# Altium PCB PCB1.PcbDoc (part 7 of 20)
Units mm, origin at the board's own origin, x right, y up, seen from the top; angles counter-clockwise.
Board outline 294.51 x 138.18 mm, 12 copper layers (Top Layer 1 _Signal, L2_GND, L3_Signals, L4_GND, L5_POWER, L6_Signals, L7_GND, L8_Signals, L9_GND, L10_POWER, L11_GND, Bottom Layer_Signals), stack 1.788 mm thick; 1254 components, 836 nets, 5699 pads, 2073 vias.
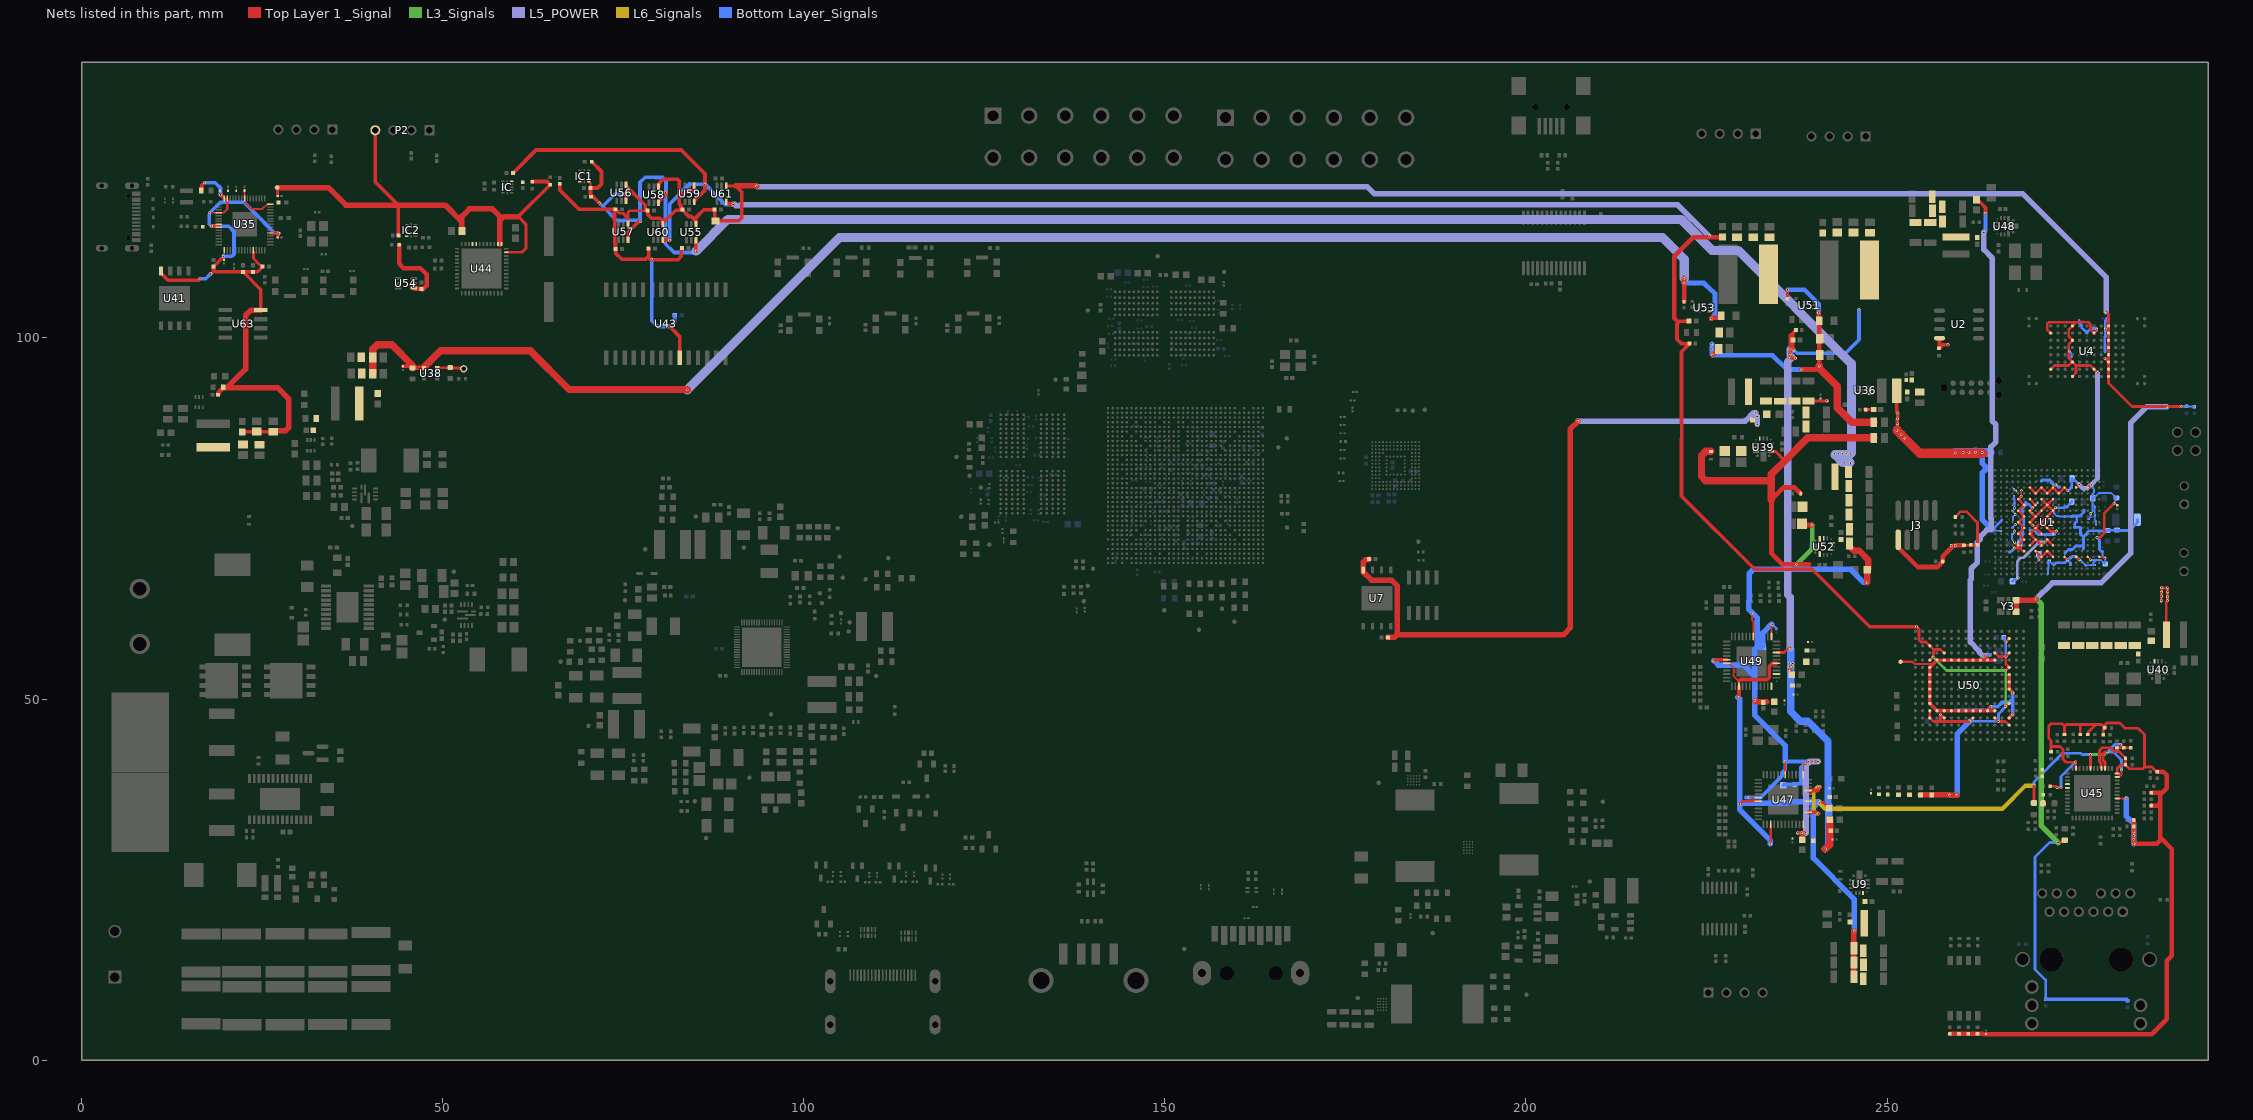
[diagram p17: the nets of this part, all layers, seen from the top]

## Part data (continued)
SW1: library part SWITCH1051, "Switch DIP", Manufacturer 1="Copal Electronics", Manufacturer Part Number 1=CHS-04TB, Supplier Part Number 1=563-1008-1-ND
SW3 SW4 SW5 SW6 SW7 SW8 SW9 SW10 SW11: library part CMP-10040-000021-1, "SWITCH TACTILE SPST-NO 0.05A 32V", Case/Package=SMD/SMT, Current Rating=50mA, Max Operating Temperature=85°C, Max Voltage Rating (DC)=32V, Min Operating Temperature=-40°C, Operating Force=4N, Package Quantity=6000, Power Rating=1W
TP2 TP6 TP7 TP8 TP9 TP10 TP13 TP14 TP15 TP16 TP17 TP18 TP20 TP22 TP23 TP25 TP27 TP28 TP29 TP31 TP35 TP36 TP37 TP38 TP39 TP41 TP42 TP43 TP45 TP46 TP48 TP49 TP50 TP51 TP52 TP53 TP54 TP55 TP56 TP57 TP59 TP60 TP61 TP62 TP63 TP64 TP65 TP66 TP67 TP68 TP71 TP72 TP74 TP75 TP76 TP81 TP82 TP83: library part CMP-00028-00002-2, "0.6mm round"
TP21: library part CON1885, "Test Point"
U1: library part MIC9729, Manufacturer 1="Microchip Technology", Operating Temperature="-40C to 85C"
U2: library part MIC9680, Manufacturer 1="Microchip Technology", Manufacturer Part Number 1=SST26WF016BT-104I/SN, Operating Temperature="-40°C ~ 85°C"
U3: "low power, high performance processor", Package=None
U4: library part IC1641, Manufacturer 1=Flexxon, Manufacturer 4=ISSI, Manufacturer Part Number 1=FEMC004GTTE7-T13-17, Manufacturer Part Number 2=FEMC004GTTE7-T13-18, Manufacturer Part Number 3=FEMC004GTTE7-T13-16, Manufacturer Part Number 4=IS21ES04G-JQLI, Operating Temperature="-40C to +85C", Package=FBGA-100, Supplier Part Number 1=3052-FEMC004GTTE7-T13-17-ND
U5: "RK806-1 Power Management IC", Package=None
U6 U63: "Security ICs / Authentication ICs ECC/ECDH, I2C, SOIC T/R", Package="SO-8 Microchip"
U7: "FLASH - NOR Memory IC 512Mb (64M x 8) SPI - Quad I/O 133 MHz 8-WSON (8x6)", Package=Package
U8: library part CMP-0078-00029-4, "IC USB FS SERIAL UART 28-SSOP", Case/Package=SSOP, Max Operating Temperature=85°C, Max Supply Voltage=5.25V, Min Operating Temperature=-40°C, Min Supply Voltage=3.3V, Operating Supply Current=15mA, Package Quantity=2000, Voltage=5V
U9 U39 U40 U48 U52: "17V VIN, 8A low-noise low-ripple buck converter with integrated ferrite-bead filter compensation 14-VQFN-HR -40 to 150", Manufacturer_Name="Texas Instruments"
U10: JLCPCB Part Class="Extended Part", Manufacturer=SANDISK(闪迪)
U11: library part SDCW2012-2-900TF
U12 U15: library part FLXC2004G-N1
U13 U14 U16 U17 U29 U33: library part ESD5341N
U18 U19: library part MP8759GD-Z
U20 U21: library part ESD5304D
U25: library part SY8089AAC
U26 U27: library part SGM2576YN5G/TR
U28: "-40℃~+125℃@(TJ) 1 120uA 3V~16V 600kHz 600mV~7V 6A Adjustable Buck Buck Built-in Yes SOT-563 DC-DC Converters ROHS", Package=SOT-563
U34: "-40℃~+125℃@(TJ) 1 3V~16V 400uA 600kHz 600mV~7V 6A Adjustable Buck Buck Built-in Yes SOT-563 DC-DC Converters ROHS", Package=SOT-563
U35: library part RP2350A
U37: library part C9002, Case=SMD3225-4P
U38: library part MIC7045, Manufacturer 1="Microchip Technology", Manufacturer Part Number 1=MIC5377YC5-TR, Operating Temperature="-40C to +125C", Supplier Part Number 1=576-3358-1-ND
U41: library part "W25Q128JVEIQ TR"
U42: library part CMP-0063-01545-2, "High Voltage System Power Management and Protection IC with PMBus, 28-pin TSSOP-EP, 2500 Reel", Manufacturer="Texas Instruments", PackageTopMarking=NSUZXYTTE#*LM5066PMH, PowerWise=Y
U43: library part CMP-0186-00060-3, "IC I/O EXPANDER I2C 16B 28SOIC", Case/Package=SOIC, Frequency=1.7MHz, Max Operating Temperature=125°C, Min Operating Temperature=-40°C, Nominal Supply Current=1mA, Operating Supply Voltage=5.5V, Package Quantity=1600
U44: "-40℃~+85℃ 1.71V~3.6V、1.71V~3.6V、2.35V~3.6V 128Byte 12Mbps 4 I2C、SPI、IrDA、RS-485、RS-232 With automatic flow control、Configurable GPIO、Auto Transceiver Direction Control、Interrupt Trigger TQFN-48-EP(7x7) UART ROHS", Case=TQFN-48-EP(7x7)
U45: library part MIC8558, Manufacturer 1="Microchip Technology", Manufacturer Part Number 1=LAN8840/PSA
U46: library part SXMH3.6864F2020F30, Case/Package=HC-49S-SMD
U47 U49: library part CMP-04874-000002-2, "IC TRANSCEIVER 1/1 48FN"
U50: library part CMP-06281-000140-1, "IC TELECOM INTERFACE 256BGA", Case/Package=BGA
U51 U53: library part TPS565247DRLR
U54 U55 U56 U57 U58 U59 U60 U61: library part CMP-00370-128857311-1, "Single channel fixed-direction level shifter 6-SC70 -40 to 125", Ambient Temperature Range High=125°C, Manufacturer Lifecycle Status=ACTIVE, Max Junction Temperature (Tj)=150°C, Min Operating Temperature=-40°C, Nominal Supply Current=2.5µA
U62: library part CMP-0069-01417-3, "Wide Range Synchronous Buck Controller, 20-pin TSSOP-EP, Pb-Free", Manufacturer="Texas Instruments", PackageTopMarking=NSUZXYTT*LM25116*MH, PowerWise=Y
USB1: library part HMT-MINIUSB-5PTP
USBC1: "USB Connectors 24 Receptacle 1 8.94*7.3mm RoHS", Package=Package
X1: library part X322524MSB4SI, "X322524MSB4SI"
Y2 Y4: library part CMP-27762-015150-1, "Crystal 25MHz ±20ppm (Tol) ±100ppm (Stability) 12pF FUND 50Ω Automotive 4-Pin Ultra Mini-CSMD T/R", Case/Package=SMD/SMT, ESR (Equivalent Series Resistance)=50R, Frequency=25MHz, Frequency Stability=100ppm, Frequency Tolerance=20ppm, LCSC=C1985412, Load Capacitance=12pF, Max Operating Temperature=125°C, Min Operating Temperature=-40°C, Ratings=AEC-Q200
Y3: library part CMP-06265-000025-1, "MEMS OSC XO 125.0000MHZ LVDS SMD", Case/Package=SMD/SMT, Frequency=125MHz, Frequency Stability=25ppm, Load Capacitance=2pF, Max Operating Temperature=85°C, Max Supply Current=32mA, Max Supply Voltage=3.6V, Min Operating Temperature=-40°C, Min Supply Voltage=2.25V, Package Quantity=1000, Ratings=AEC-Q100

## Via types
v1: diameter 0.4, hole 0.2, Top Layer 1 _Signal to Bottom Layer_Signals, 2009 vias
v2: diameter 0.508, hole 0.254, Top Layer 1 _Signal to Bottom Layer_Signals, 36 vias
v3: diameter 0.5, hole 0.2, Top Layer 1 _Signal to Bottom Layer_Signals, 12 vias
v4: diameter 1.27, hole 0.711, Top Layer 1 _Signal to Bottom Layer_Signals, 6 vias
v5: diameter 0.3, hole 0.2, Top Layer 1 _Signal to Bottom Layer_Signals, 5 vias
v6: diameter 0.254, hole 0.2, Top Layer 1 _Signal to Bottom Layer_Signals, 3 vias
v7: diameter 0.305, hole 0.2, Top Layer 1 _Signal to Bottom Layer_Signals, 1 vias
v8: diameter 0.254, hole 0.152, Top Layer 1 _Signal to Bottom Layer_Signals, 1 vias

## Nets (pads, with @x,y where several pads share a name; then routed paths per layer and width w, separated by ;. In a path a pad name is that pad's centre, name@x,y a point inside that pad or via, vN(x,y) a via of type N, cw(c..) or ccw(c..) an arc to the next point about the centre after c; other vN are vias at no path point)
0V9: C132.2 C133.2 C136.1 C137.1 C138.1 C139.1 C140.1 C141.1 C142.1 C143.1 C144.1 C145.1 C146.1 C147.1 C148.1 C149.1 C150.1 C151.1 C152.1 C153.1 C154.1 C155.1 C156.1 C190.1 C191.1 C491.2 C635.2 C636.2 C638.2 C639.2 C640.2 FB4.1 FB5.1 FB6.1 FB7.1 L23.2 R158.2 R160.1 U1.J6 U1.J8 U1.J10 U1.J12 U1.J14 U1.K7 U1.K9 U1.K11 U1.K13 U1.L6 U1.L8 U1.L10 U1.L12 U1.L14 U1.M7 U1.M9 U1.M11 U1.M13 U1.N6 U1.N8 U1.N10 U1.N12 U1.N14 U40.4 | length 84.1
  Top Layer 1 _Signal w0.381: U1.N14@269.781,71.28 U1.M13@270.581,72.08 ; U1.N6@269.781,77.68 U1.M7@270.581,76.88 270.568,76.88 270.127,76.439 v1(270.122,76.439) 270.122,76.434 269.781,76.093 U1.N8@269.781,76.08 269.781,75.975 270.07,75.686 v1(270.07,75.681) ; v1(270.2,74.022) 270.2,74.027 269.781,74.446 U1.N10@269.781,74.48 270.473,75.172 270.473,75.277 v1(270.07,75.681) ; U1.L12@271.381,72.88 U1.M11@270.581,73.68 ; U1.L6@271.381,77.68 U1.K7@272.181,76.88 ; v1@271.863,71.762 U1.K13@272.181,72.08 U1.J14@272.981,71.28 ; v1(271.886,71.74) 271.881,71.74 271.421,71.28 U1.L14@271.381,71.28 U1.M13@270.581,72.08 ; U1.J12@272.981,72.88 272.62,73.241 ; U1.J10@272.981,74.48 U1.K9@272.181,75.28 ; U1.J6@272.981,77.68 U1.K7@272.181,76.88 ; v1(273.316,76.478) 273.316,76.472 272.981,76.137 U1.J8@272.981,76.08 ; v1(273.459,73.251) 273.454,73.251 273.443,73.241 272.62,73.241 ; v1(287.967,63.59) 287.967,63.595 287.995,63.623 287.995,64.261 v1(287.999,64.264) v1(287.999,64.813) 287.999,64.818 288.027,64.846 288.027,65.408 v1(288.03,65.412) 288.036,65.412 288.067,65.38 v1(288.863,65.38) 288.863,65.375 288.854,65.366 288.854,64.829 v1(288.85,64.825) 288.85,64.82 288.844,64.814 v1(288.844,64.157) 288.844,64.152 288.828,64.137 288.828,63.619 v1(288.825,63.615) 288.825,63.59 288.674,63.439 L23.2@288.674,58.913 ; v1(270.07,75.681) 270.075,75.681 270.476,75.28 U1.M9@270.581,75.28 U1.L8@271.381,76.08 U1.K7@272.181,76.88 ; U1.M13@270.581,72.08 U1.N12@269.781,72.88 U1.M11@270.581,73.68 ; U1.M11@270.581,73.68 U1.L10@271.381,74.48 ; U1.L10@271.381,74.48 U1.K11@272.181,73.68 272.62,73.241 ; U1.L10@271.381,74.48 U1.K9@272.181,75.28 ; U1.K9@272.181,75.28 U1.J8@272.981,76.08 ; U1.K7@272.181,76.88 U1.J8@272.981,76.08
  L5_POWER w0.381: v1(268.15,66.798) 268.15,66.804 268.022,66.932 268.022,69.007 268.203,69.188 268.203,69.287 268.481,69.565 268.903,69.565 271.078,71.74 v1(271.886,71.74)
  Bottom Layer_Signals w0.254: v1(273.316,76.478) 273.316,76.438 273.123,76.245 273.123,75.79 C137.1@273.11,75.777 273.11,75.767 273.289,75.587 273.289,75.539 273.485,75.343 273.918,75.343 274.001,75.259 C141.1@274.576,75.259 274.589,75.272 275.018,75.272 275.088,75.343 275.144,75.287 275.638,75.287 C146.1@275.651,75.274
  Bottom Layer_Signals w0.381: FB6.1@267.381,66.293 267.381,66.338 267.59,66.547 267.894,66.547 268.145,66.798 v1(268.15,66.798) 268.15,66.792 v1@268.026,66.668 ; FB5.1@268.371,71.513 268.371,71.479 268.389,71.461 268.537,71.609 268.537,72.318 268.737,72.519 268.737,72.695 268.748,72.705 C148.1@268.748,73.766 268.92,73.939 C144.1@268.92,74.922 268.92,75.343 268.739,75.523 C150.1@268.739,75.944 268.739,76.362 269.193,76.816 C142.1@269.193,77.233 269.446,76.981 269.574,76.981 270.117,76.439 v1(270.122,76.439) ; C143.1@269.813,73.353 270.415,73.353 C152.1@270.979,72.788 271.845,72.788 271.909,72.725 C151.1@271.967,72.725 272.03,72.788 273.181,72.788 C138.1@273.186,72.793 273.186,72.973 273.459,73.246 v1(273.459,73.251) ; C191.1@271.233,71.264 271.405,71.264 271.881,71.74 v1(271.886,71.74) ; v1(273.316,76.478) 274.467,76.478 274.586,76.597 274.982,76.597 274.982,76.701 274.997,76.701 274.997,76.729 275.004,76.729 275.564,77.289 FB4.1@275.564,77.334 ; C154.1@274.65,70.14 274.65,70.23 275.137,70.717 275.659,70.717 276.126,71.183 277.034,71.183 277.195,71.022 ; C146.1@275.651,75.274 275.731,75.354 276.286,75.354 ; C190.1@277.165,70.759 277.195,70.789 277.195,71.022 ; C155.1@277.278,76.158 277.278,75.911 C156.1@276.773,75.406 276.722,75.354 276.286,75.354 ; C133.2@280.542,73.346 C133.2@280.579,73.384 ; FB7.1@284.673,74.823 284.673,74.448 283.572,73.346 281.911,73.346 C132.2@281.836,73.421 281.799,73.384 C133.2@280.579,73.384 ; 276.286,75.354 276.286,74.612 275.979,74.305 C140.1@275.979,73.767 275.986,73.774 C136.1@276.744,73.774 276.803,73.715 C153.1@276.803,72.818 277.195,72.426 ; 277.195,71.022 277.195,71.183 C139.1@277.195,71.772 277.195,72.426 ; 277.195,72.426 277.587,72.818 C149.1@277.593,72.818 277.708,72.934 277.708,73.082 277.92,73.293 279.214,73.293 279.241,73.266 280.461,73.266 C133.2@280.579,73.384
1V0_VSC: C531.2 C532.2 C533.2 C534.2 C535.2 C536.2 C611.2 C613.2 C614.2 C615.1 C616.1 C617.1 L24.2 R54.1 R161.1 TP8.1 U48.4 U50.C7 U50.C8 U50.C9 U50.C13 U50.E5 U50.E12 U50.F5 U50.F12 U50.G5 U50.G12 U50.H5 U50.H12 U50.J5 U50.J12 U50.K5 U50.K12 U50.L5 U50.L12 U50.M5 U50.M12 U50.N5 U50.N12 U50.P6 U50.P7 U50.P8 U50.P9 U50.P10 U50.P11 | length 112.9
  Top Layer 1 _Signal w0.3: TP8.1@251.884,55.156 253.503,55.156 253.792,54.867 256.362,54.867 256.385,54.845
  Top Layer 1 _Signal w0.508: R54.1@262.362,119.122 262.362,119.099 262.587,118.873 262.611,118.873 262.639,118.846 262.837,118.846 263.644,118.038 v1(263.644,117.264) ; v1(263.457,55.958) 264.036,55.379 U50.E5@264.919,55.379 ; U50.F5@263.919,55.379 U50.G5@262.919,55.379 U50.H5@261.919,55.379 U50.J5@260.919,55.379 U50.K5@259.919,55.379 U50.L5@258.919,55.379 U50.M5@257.919,55.379 U50.N5@256.919,55.379 256.385,54.845 U50.P6@255.919,54.379 U50.P7@255.919,53.379 U50.P8@255.919,52.379 U50.P9@255.919,51.379 U50.P10@255.919,50.379 U50.P11@255.919,49.379 U50.N12@256.919,48.379 256.949,48.409 257.889,48.409 U50.M12@257.919,48.379 U50.L12@258.919,48.379 U50.K12@259.919,48.379 U50.J12@260.919,48.379 U50.H12@261.919,48.379 U50.G12@262.919,48.379 U50.F12@263.919,48.379 ; v1(264.381,48.94) 264.381,48.841 U50.F12@263.919,48.379 ; U50.E12@264.919,48.379 U50.F12@263.919,48.379 ; U50.C13@266.919,47.379 266.919,47.398 v1(267.386,47.864) ; U50.C7@266.919,53.379 U50.C8@266.919,52.379 U50.C9@266.919,51.379 267.368,50.93 v1(267.368,50.874)
  L5_POWER w0.762: v1(263.422,114.601) 263.422,112.217 264.571,111.068 264.571,99.808 264.541,99.778 264.541,88.519 265.074,87.985 265.074,85.607 264.366,84.899 264.366,75.007 264.415,74.957 264.415,73.634 264.203,73.422 263.829,73.422 262.929,72.522 262.929,72.148 262.499,71.718 262.499,68.886 261.664,68.051 261.664,66.592 261.535,66.464 261.535,57.881 262.747,56.668 262.747,56.504 263.293,55.958 v1(263.457,55.958)
  Bottom Layer_Signals w0.508: C614.2@259.443,48.456 263.897,48.456 v1(264.381,48.94) 265.349,48.94 265.925,49.516 266.893,49.516 267.368,49.991 ; v1(263.422,114.601) 263.644,114.824 v1(263.644,117.264) ; v1(263.457,55.958) 263.643,56.144 264.174,56.144 C611.2@264.178,56.148 ; v1(267.368,50.874) 267.386,50.857 v1(267.386,47.864)
1V1: C26.1 C202.2 C375.1 C376.1 C377.1 C378.1 C379.1 C490.2 C522.2 C523.2 C524.2 C525.2 C650.2 C652.1 C660.1 C664.2 C666.1 FB24.2 FB26.2 L15.2 R43.1 R50.1 U9.4 U45.23 U45.27 U45.31 U45.40 U47.6 U47.31 U47.39 U49.6 U49.31 U49.39 | length 141.5
  Top Layer 1 _Signal w0.254: U49.31@227.79,54.955 228.184,54.955 228.73,54.409 228.73,53.215 229.491,52.454 U49.39@229.491,51.754
  Top Layer 1 _Signal w0.3: U45.23@281.874,39.203 282.064,39.203 282.191,39.329 282.239,39.329 282.458,39.548 282.458,40.146 v1(282.474,40.162)
  Top Layer 1 _Signal w0.381: v1(229.574,35.423) 229.579,35.423 229.991,35.835 U47.31@232.187,35.835 ; v1(233.853,29.96) 233.887,29.995 U47.39@233.887,32.634 ; v1(240.687,35.658) 241.246,35.658 C26.1@241.997,34.907 ; FB26.2@270.349,35.589 v1(270.349,38.01) ; U45.31@278.174,40.403 v1(278.174,42.305) ; U45.27@280.174,40.403 280.174,41.241 279.898,41.517 279.898,42.456 280.121,42.679 v1(280.516,42.679) ; C376.1@281.842,43.238 281.845,43.236 282.793,43.236 C377.1@282.795,43.233 ; v1(282.324,43.734) 282.329,43.734 282.821,43.242 283.724,43.242 C378.1@283.733,43.252
  Top Layer 1 _Signal w0.508: v1(229.354,50.24) 229.491,50.377 U49.39@229.491,51.754 ; 229.491,52.454 229.746,52.709 233.423,52.709 233.678,52.965 233.678,54.498 234.093,54.912 234.649,54.912 U49.6@234.691,54.955
  Top Layer 1 _Signal w0.762: C524.2@245.416,11.556 245.416,17.821 v1(245.454,17.858)
  L3_Signals w0.381: v1(278.174,42.305) 280.136,42.305 280.511,42.679 v1(280.516,42.679)
  L6_Signals w0.6: v1(240.687,35.658) 240.687,35.544 241.445,34.787 265.946,34.787 269.169,38.01 v1(270.349,38.01)
  Bottom Layer_Signals w0.381: v1(270.349,38.01) 270.349,38.524 274.318,42.493 276.8,42.493 276.988,42.305 v1(278.174,42.305) ; v1(282.324,43.734) 281.571,43.734 v1(280.516,42.679) 281.371,42.679 282.474,41.576 v1(282.474,40.162)
  Bottom Layer_Signals w0.762: v1(229.354,50.24) 229.574,50.019 v1(229.574,35.423) ; v1(233.853,29.96) 233.853,30.392 229.574,34.67 v1(229.574,35.423) ; v1(245.454,17.858) 245.454,22.307 239.79,27.971 239.79,34.988 240.46,35.658 v1(240.687,35.658) 240.555,35.79 236.461,35.79 236.235,35.564 229.715,35.564 v1(229.574,35.423)
1V2: C78.1 C79.1 C80.1 C81.1 C82.1 C83.1 C84.1 C85.1 C86.1 C87.1 C88.2 C486.1 C487.2 L9.2 R139.1 R141.2 U1.P7 U1.P9 U1.P11 U1.P13 U1.P15 U1.R6 U1.R8 U1.R10 U1.R12 U1.R14 | length 58.9
  Top Layer 1 _Signal w0.254: v1(268.583,78.082) 268.58,78.086 268.58,78.646 268.595,78.662 268.595,78.825 v1(268.623,78.853)
  Top Layer 1 _Signal w0.381: v1(267.622,70.894) 267.628,70.894 267.639,70.883 267.963,70.883 267.999,70.919 268.363,70.919 268.802,70.48 U1.P15@268.981,70.48 ; v1(267.652,71.69) 267.657,71.69 268.067,71.28 U1.R14@268.181,71.28 ; U1.R6@268.181,77.68 U1.P7@268.981,76.88 U1.R8@268.181,76.08 U1.P9@268.981,75.28 U1.R10@268.181,74.48 U1.P11@268.981,73.68 U1.R12@268.181,72.88 U1.P13@268.981,72.08 U1.R14@268.181,71.28 ; U1.R6@268.203,77.658 268.476,77.93 268.476,77.969 268.583,78.077 v1(268.583,78.082) ; 268.452,71.009 U1.R14@268.181,71.28
  Top Layer 1 _Signal w0.508: v1(251.362,87.206) 251.433,87.277 v1(251.433,88.093) 251.423,88.103 v1(251.423,88.805) 251.486,88.868 v1(251.486,89.601) 251.362,89.725 L9.2@251.362,92.706
  Top Layer 1 _Signal w1.27: v1(251.362,87.206) v1(251.97,86.597) v1(252.505,86.063) 254.53,84.038 v1@263.249,84.038
  Bottom Layer_Signals w0.254: 264.666,73.428 264.779,73.316 265.094,73.316 265.113,73.297 C78.1@265.752,73.297 ; C84.1@267.294,72.746 267.281,72.733 267.281,72.317 267.278,72.313 267.278,72.103 267.652,71.729 v1(267.652,71.69) ; C84.1@267.333,72.708 267.64,73.015 267.64,73.22 v1(267.668,73.248) ; C83.1@267.374,73.77 267.374,73.78 267.75,74.156 v1(267.774,74.156) ; C79.1@267.446,74.843 267.446,75.231 267.75,75.534 267.723,75.562 267.723,75.685 267.398,76.01 C87.1@267.398,76.02 267.398,76.03 267.652,76.285 v1(267.652,76.459) 267.652,77.04 267.651,77.041 267.651,77.135 C86.1@267.638,77.148 267.638,77.679 267.59,77.726 267.59,78.101 C80.1@267.577,78.114 ; C82.1@267.554,79.05 267.554,79.04 267.803,78.79 v1(267.833,78.79)
  Bottom Layer_Signals w0.381: 264.666,73.428 264.666,73.556 C85.1@265.897,74.786 ; C81.1@266.931,70.343 267.071,70.343 v1(267.622,70.894)
  Bottom Layer_Signals w0.762: v1(263.189,84.137) 263.189,84.102 263.189,82.628 263.569,82.247 263.569,81.697 263.189,81.316 263.189,74.794 264.554,73.428 264.666,73.428
  Bottom Layer_Signals w1.27: v1(259.439,84.103) 259.441,84.102 260.495,84.102 261.33,84.102 v1@262.266,84.102 ; v1(262.266,84.17) v1@262.266,84.102 ; C88.2@264.217,84.154 263.241,84.154 263.189,84.102 v1@262.266,84.102
  other v1: 267.751,75.534 260.495,84.137 261.33,84.144
1V8: C11.2 C12.2 C13.2 C14.2 C89.1 C90.1 C91.1 C92.1 C93.1 C94.1 C95.1 C96.1 C97.2 C98.1 C99.1 C100.1 C101.1 C102.1 C103.1 C104.1 C105.1 C106.2 C182.1 C183.1 C353.2 C381.1 C382.1 C383.1 C384.1 C385.1 C538.2 C539.2 C540.2 C597.2 C600.2 FB1.2 FB2.1 FB3.1 J3.1 L8.2 R1.2 R2.2 R5.2 R7.2 R8.2 R10.1 R12.1 R13.1 R15.1 R42.1 R72.2 R73.2 R101.2 R184.1 R185.1 R374.2 R376.2 R381.2 R383.2 R385.2 R387.2 R389.2 R391.2 R393.2 R395.2 U1.A16 U1.C4 U1.C16 U1.E4 U1.E16 U1.G4 U1.G16 U1.H5 U1.J4 U1.J16 U1.K5 U1.K15 U1.L4 U1.L16 U1.M5 U1.M15 U1.N4 U2.8 U4.H3 U4.H8 U4.L2 U4.L4 U4.L7 U4.L9 U4.P3 U4.P8 U7.8 U39.4 U45.17 U45.24 U45.28 U45.35 U45.41 | length 374.9
  Top Layer 1 _Signal w0.254: U1.C16@277.781,69.68 v1(278.197,69.264) ; U1.A16@279.381,69.68 279.98,69.68 v1(280.158,69.501) ; v1(281.412,77.062) 281.63,77.062 281.86,76.833 C183.1@281.87,76.833 ; U45.17@281.874,36.203 283.088,36.203 v1(283.098,36.212)
  Top Layer 1 _Signal w0.381: C600.2@239.138,91.25 v1@241.665,91.25 ; v1(258.897,71.242) v1(259.445,71.242) ; R5.2@259.471,75.197 259.471,75.214 260.199,75.942 260.995,75.942 262.527,74.41 262.527,71.406 R1.2@262.461,71.339 ; R7.2@260.65,71.288 261.543,71.288 261.595,71.339 R42.1@261.611,71.339 R1.2@262.461,71.339 ; R1.2@262.524,71.359 262.48,71.359 R1.2@262.461,71.339 ; U1.N4@269.781,79.28 U1.M5@270.581,78.48 U1.L4@271.381,79.28 U1.K5@272.181,78.48 U1.J4@272.981,79.28 ; U1.M15@270.581,70.48 U1.L16@271.381,69.68 ; v1(270.951,69.25) U1.L16@271.381,69.68 ; C385.1@272.571,37.913 273.383,37.913 273.53,37.766 v1(273.535,37.766) 273.539,37.762 274.055,37.762 274.086,37.732 v1(274.091,37.732) ; U4.P8@272.672,95.669 272.69,95.669 273.191,96.169 275.154,96.169 275.653,96.669 U4.L7@275.672,96.669 ; U4.P3@272.672,100.669 272.672,100.687 272.172,101.187 272.172,101.92 272.422,102.17 276.191,102.17 ; R374.2@272.714,42.69 272.714,43.19 ; U1.J16@272.981,69.68 U1.K15@272.181,70.48 U1.L16@271.381,69.68 ; v1(273.371,79.671) U1.J4@272.981,79.28 ; R385.2@274.567,45.088 274.567,46.246 ; U1.G16@274.581,69.68 274.998,69.263 v1(275.011,69.263) ; v1(274.978,78.883) U1.G4@274.581,79.28 U1.H5@273.781,78.48 U1.J4@272.981,79.28 ; U4.L9@275.672,94.669 275.672,94.687 276.172,95.188 276.172,96.152 276.19,96.169 ; U45.35@276.174,40.403 276.124,40.454 v1(276.124,41.276) 276.119,41.276 276.085,41.242 274.774,41.242 274.353,41.664 274.353,43.01 273.938,43.425 272.949,43.425 272.714,43.19 ; U1.E16@276.181,69.68 276.594,69.267 v1(276.643,69.267) ; U1.E4@276.181,79.28 v1(276.602,79.701) ; R383.2@276.77,45.088 276.77,46.246 276.994,46.469 ; U1.C4@277.781,79.28 277.897,79.28 v1(278.278,79.661) ; R381.2@277.801,45.088 277.817,45.088 277.864,45.135 277.864,45.41 278.923,46.469 ; U4.H3@278.672,100.669 U4.H3@278.672,100.687 ; v1(279.04,101.216) 279.036,101.213 279.036,101.052 U4.H3@278.672,100.687 ; v1(279.091,72.362) 279.095,72.366 279.488,72.366 280.085,72.963 280.085,75.736 v1(281.412,77.062) ; v1(279.148,95.192) U4.H8@278.672,95.669 278.653,95.669 278.152,96.169 276.19,96.169 ; U45.28@279.674,40.403 279.624,40.454 279.624,41.134 279.433,41.325 279.433,42.872 279.552,42.99 279.552,43.019 279.775,43.242 281.005,43.242 281.52,42.727 282.109,42.727 283.024,41.811 C383.1@283.024,41.795 C382.1@283.024,40.887 ; R376.2@279.944,45.043 279.944,45.789 280.138,45.983 C384.1@280.138,45.999 ; U45.24@281.874,39.703 281.874,40.403 282.358,40.887 C382.1@283.024,40.887 ; R391.2@287.42,39.948 287.42,39.964 287.373,40.011 287.207,40.011 286.984,40.235 286.984,40.272 286.671,40.584 285.665,40.584 ; 272.714,43.19 272.714,44.241 272.4,44.555 272.4,46.264 272.715,46.579 274.234,46.579 274.567,46.246 ; 274.567,46.246 274.79,46.469 276.994,46.469 ; U4.L7@275.672,96.669 275.672,96.687 275.172,97.187 275.172,98.136 275.239,98.202 v1(275.239,98.207) 275.239,98.212 275.172,98.279 275.172,99.151 275.672,99.65 U4.L4@275.672,99.669 275.672,99.687 275.172,100.187 275.172,101.151 275.672,101.65 U4.L2@275.672,101.669 275.69,101.669 276.191,102.17 ; U4.L7@275.672,96.669 275.69,96.669 276.19,96.169 ; 276.191,102.17 277.877,102.17 278.171,101.875 278.171,101.188 U4.H3@278.672,100.687 ; 276.994,46.469 278.923,46.469 ; 278.923,46.469 279.685,46.469 280.138,46.016 C384.1@280.138,45.999 ; C384.1@280.138,45.999 280.17,46.032 280.17,46.458 280.394,46.682 282.252,46.682 282.976,45.958 284.771,45.958 285.665,45.064 285.665,40.584 ; C382.1@283.024,40.887 283.024,40.87 283.538,40.357 285.437,40.357 285.665,40.584
  Top Layer 1 _Signal w0.508: v1@241.665,91.25 241.679,91.264 v1(241.679,91.303) ; R2.2@257.201,98.551 R2.2@257.243,98.551 ; U2.8@257.262,99.962 257.262,98.57 R2.2@257.243,98.551 ; v1(258.444,99.069) 257.761,99.069 R2.2@257.243,98.551
  Top Layer 1 _Signal w0.635: J3.1@251.551,72.048 251.551,70.981 254.252,68.279 256.988,68.279 257.387,68.679 257.387,68.742 R8.2@257.697,69.052 257.697,69.759 259.18,71.242 v1(259.445,71.242) 259.567,71.242 259.612,71.288 R7.2@260.65,71.288 ; R15.1@258.701,3.622 R13.1@259.971,3.622 R12.1@261.254,3.622 R10.1@262.524,3.622 263.347,3.622 263.388,3.581 286.663,3.581 288.716,5.634 288.716,13.74 289.43,14.454 289.43,29.239 287.811,30.857 ; R393.2@284.173,33.237 284.173,32.351 C381.1@284.179,32.345 v1@284.179,29.964 ; v1(284.178,29.963) v1@284.179,29.964 ; R387.2@286.572,35.245 287.439,35.245 287.811,35.617 ; R389.2@286.573,37.013 288.088,37.013 288.71,37.635 288.71,39.473 288.235,39.948 R391.2@287.42,39.948 ; 287.811,37.013 287.811,35.617 ; v1@284.179,29.964 287.345,29.964 287.811,30.431 287.811,30.857 ; 287.811,30.857 287.811,35.617
  Top Layer 1 _Signal w0.762: R73.2@178.269,69.357 178.185,69.272 177.781,69.272 177.47,68.961 U7.8@177.47,67.857 177.47,67.607 178.609,66.468 181.376,66.468 182.147,65.697 182.147,58.889 ; R72.2@180.884,58.519 181.777,58.519 182.147,58.889 ; v1(207.193,88.456) 206.132,87.395 206.132,67.194 206.154,67.172 206.154,61.764 206.132,61.741 206.132,59.847 205.173,58.889 182.147,58.889
  L5_POWER w0.635: v1(276.602,79.701) 276.602,79.654 277.074,79.183 277.738,79.183 278.216,79.661 v1(278.278,79.661) ; v1@278.304,79.695 279.148,80.539 v1(279.148,95.192)
  L5_POWER w0.762: v1(207.193,88.456) 230.354,88.456 231.538,89.64 v1(231.806,89.64) 231.806,89.343 v1(232.026,89.123) v1(232.026,88.032)
  Bottom Layer_Signals w0.254: C102.1@272.27,67.378 272.27,67.95 272.356,68.036 272.356,68.239 272.372,68.255 272.372,69 R101.2@272.47,69.098 ; R101.2@272.47,69.081 272.581,68.971 272.597,68.971 272.903,68.665 272.993,68.665 273.076,68.582 C96.1@273.099,68.582 ; v1(275.239,98.207) 275.239,98.168 275.517,97.89 C11.2@275.517,97.358 ; v1(276.602,79.701) 276.63,79.673 276.63,79.463 277.044,79.049 277.092,79.049 277.272,78.87 C105.1@277.282,78.87 ; v1(276.643,69.267) 276.671,69.239 276.796,69.239 277.515,68.521 278.145,68.521 278.183,68.558 278.585,68.558 ; C98.1@277.935,74.923 277.945,74.923 277.958,74.936 277.958,74.946 278.184,75.172 278.184,75.643 v1(278.212,75.671) 278.212,75.711 278.47,75.968 278.47,76.895 ; v1(278.197,69.264) 278.221,69.24 278.955,69.24 C92.1@278.968,69.227 ; v1(278.278,79.661) 278.278,79.622 278.47,79.43 278.47,79.196 278.656,79.009 278.656,78.669 278.47,78.483 278.47,77.825 FB2.1@278.488,77.807 278.47,77.789 278.47,76.895 ; FB2.1@278.543,77.752 278.737,77.946 278.748,77.946 279.327,78.525 281.054,78.525 281.723,77.856 C97.2@281.749,77.856 ; C94.1@278.767,76.597 278.47,76.895 ; C90.1@278.769,75.435 278.769,75.425 278.754,75.41 278.754,74.833 278.952,74.636 278.952,74.22 C89.1@278.965,74.207 ; C90.1@278.768,75.435 C94.1@278.767,76.597 ; C101.1@278.786,68.57 278.585,68.57 278.585,68.855 278.945,69.214 278.955,69.214 C92.1@278.968,69.227 ; C91.1@279.843,70.426 279.843,69.856 280.158,69.541 v1(280.158,69.501) 280.158,69.462 280.212,69.408 C106.2@280.212,68.722 280.136,68.722 279.631,69.227 C92.1@278.968,69.227 ; v1(281.412,77.062) 281.412,77.102 281.53,77.219 281.53,77.637 C97.2@281.749,77.856 ; C97.2@281.773,77.856 C97.2@281.749,77.856
  Bottom Layer_Signals w0.381: v1(270.951,69.25) 270.954,69.253 270.954,69.976 FB3.1@271.007,70.029 ; C95.1@271.378,80.232 271.471,80.325 272.531,80.325 272.692,80.164 272.692,80.017 C93.1@272.808,79.901 273.034,79.674 273.368,79.674 v1(273.371,79.671) 273.377,79.671 273.678,79.369 C104.1@273.902,79.369 ; C96.1@273.099,68.569 273.391,68.861 274.604,68.861 275.003,69.259 v1@275.006,69.259 ; v1(274.091,37.732) 274.091,39.243 v1(276.124,41.276) ; v1(274.978,78.883) 274.982,78.887 275.129,78.887 C99.1@275.577,79.335 275.577,80.475 FB1.2@275.639,80.537 275.847,80.33 275.973,80.33 v1(276.602,79.701) ; v1@275.007,69.259 275.011,69.254 275.015,69.254 275.015,69.23 275.4,68.845 C100.1@275.4,68.59 ; v1(275.011,69.263) 275.017,69.263 275.297,69.543 275.448,69.543 275.673,69.768 276.137,69.768 276.638,69.267 v1(276.643,69.267) ; C14.2@276.613,102.382 276.613,102.092 276.954,101.751 276.954,101.462 C13.2@277.66,100.756 278.207,101.304 278.947,101.304 279.035,101.216 v1(279.04,101.216) ; v1(279.091,72.362) 279.419,72.035 279.419,70.702 279.643,70.478 279.791,70.478 C91.1@279.843,70.426
  Bottom Layer_Signals w0.762: v1(283.098,36.212) 283.098,33.796 284.178,32.715 v1(284.178,31.594) v1(284.178,31.078) v1(284.178,29.963)
  other v1: 284.165,30.576
1V8_DP: C24.1 C27.2 C28.1 C29.1 C620.2 C621.2 C622.2 C623.2 C624.2 C625.2 C647.1 C648.1 C653.2 C654.1 C655.1 C656.2 C657.1 C658.1 C661.2 C662.1 IC1.1 L26.2 R231.1 R232.1 R283.1 U47.13 U47.18 U47.30 U47.48 U49.13 U49.18 U49.30 U49.48 U52.4 U55.6 U56.6 U57.6 U58.6 | length 350.3
  Top Layer 1 _Signal w0.254: v1(230.893,36.381) 230.94,36.335 U47.30@232.187,36.335 ; v1(231.296,61.85) 231.296,60.962 231.491,60.766 U49.18@231.491,58.655 ; U47.18@235.887,39.535 235.887,41.336 v1(235.894,41.342) ; U47.13@238.388,39.535 238.388,40.836 238.899,41.348 v1(240.432,41.348)
  Top Layer 1 _Signal w0.3: IC1.1@70.202,121.618 70.252,121.618 70.467,121.403 R283.1@70.467,120.771 ; U49.13@233.991,58.655 233.991,60.2 234.089,60.298 v1(234.089,60.326)
  Top Layer 1 _Signal w0.4: v1(75.228,119.885) 75.395,119.718 U56.6@75.395,118.991
  Top Layer 1 _Signal w0.508: C647.1@70.642,124.397 71.981,123.058 71.981,121.329 71.423,120.771 R283.1@70.467,120.771 70.467,119.902 v1(71.705,118.664) ; U57.6@75.658,113.599 75.707,113.648 75.707,114.671 77.18,116.144 v1(77.377,116.144) ; U58.6@79.894,118.739 79.894,118.881 80.856,119.843 v1(80.856,120.202) ; U55.6@85.064,113.53 85.064,112.045 v1(85.087,112.022) ; v1(225.986,55.268) 226.025,55.268 226.212,55.455 U49.30@227.79,55.455 ; v1(237.626,31.458) 238.176,31.458 v1(238.201,31.483) ; C29.1@238.261,30.523 238.201,30.583 v1(238.201,31.483) ; v1(238.765,31.475) 238.757,31.483 v1(238.201,31.483)
  Top Layer 1 _Signal w0.762: v1(231.675,49.775) 231.848,49.602 233.33,49.602
  Top Layer 1 _Signal w0.889: C620.2@244.782,71.54 244.782,71.165 245.433,70.513 246.148,70.513 247.375,69.285 247.375,68.019 247.362,68.005 247.362,67.982 247.3,67.921 R231.1@247.277,67.921 247.277,66.19 v1(247.237,66.15)
  L5_POWER w0.889: v1(238.765,31.475) 238.777,31.488 238.777,36.817 238.765,36.83 238.765,40.827 239.285,41.348 v1(240.432,41.348)
  L5_POWER w1.27: v1(85.087,112.022) 89.486,116.42 221.464,116.42 225.767,112.117 229.385,112.117 245.065,96.436 245.065,84.111 244.777,83.823 242.805,83.823 243.872,82.755 244.15,82.755 v1(244.17,82.736) 244.866,82.736 v1@244.872,82.729
  Bottom Layer_Signals w0.381: v1(234.089,60.326) 234.675,59.739 C662.1@234.675,59.706
  Bottom Layer_Signals w0.508: v1(71.705,118.664) 72.147,118.222 ; v1(75.228,119.885) 73.81,119.885 72.147,118.222 ; v1(77.377,116.144) v1@77.333,116.188 ; v1(85.087,112.022) 84.891,111.825 82.055,111.825 80.825,113.056 80.825,118.773 80.856,118.805 v1(80.856,120.202) 80.921,120.267 80.921,121.739 80.452,122.208 79.536,122.208 79.5,122.244 78.034,122.244 77.333,121.543 v1@77.333,116.188 ; 230.433,36.369 230.893,36.369 232.505,36.369 235.466,39.33 235.466,39.797 235.894,40.224 v1(235.894,41.342) 238.657,41.342 238.893,41.342 ; C24.1@235.619,38.038 235.765,38.183 C27.2@237.192,38.183 ; C27.2@237.192,38.222 237.224,38.254 238.034,38.254 238.09,38.309 ; C28.1@238.697,38.322 238.102,38.321 238.09,38.309 ; v1(240.432,41.348) 240.426,41.342 239.726,41.342 v1(239.188,41.342) 238.893,41.342 ; 72.147,118.222 74.083,116.286 74.541,116.286 74.581,116.247 75.027,116.247 75.066,116.286 77.235,116.286 v1@77.333,116.188 ; 238.09,38.309 238.09,40.539 238.657,41.106 238.893,41.342
  Bottom Layer_Signals w0.762: v1(225.986,55.268) 226.089,55.268 226.66,54.698 C661.2@228.9,54.698 228.916,54.682 230.147,54.682 231.675,53.154 ; v1@234.026,60.376 232.81,59.16 C658.1@232.81,57.263 232.741,57.194 231.995,57.194 ; v1(235.894,41.342) 235.894,43.555 231.675,47.773 v1(231.675,49.775) 231.675,53.154 ; v1(247.237,66.15) 246.734,66.15 244.915,67.969 231.524,67.969 230.901,67.346 230.901,63.628 230.861,63.588 230.861,62.421 231.363,61.918 231.995,61.286 231.995,57.194 ; 231.675,53.154 231.675,56.874 231.995,57.194
  other v1: 238.776,40.988 239.726,41.355 244.944,82.729 242.68,83.959 243.246,83.965 243.799,83.978 244.892,83.972 244.352,84.004
2V5: R335.2 TP21.1 U38.5 | length 3.8
  Top Layer 1 _Signal w0.381: U38.5@49.245,95.859 49.27,95.884 51.021,95.884 R335.2@51.046,95.909 51.135,95.82 52.82,95.82 TP21.1@52.909,95.731
2V5_DP: C25.1 C649.2 C651.1 C659.1 C663.2 C665.1 C670.1 C671.1 C672.1 C673.1 C674.1 L27.2 R254.2 U47.3 U47.9 U49.3 U49.9 | length 114.1
  Top Layer 1 _Signal w0.254: v1(236.404,54.023) 236.425,54.045 236.425,54.447 v1(236.447,54.469) 236.458,54.48 236.458,54.937 v1(236.469,54.948) 236.482,54.935 236.946,54.935 v1(236.959,54.921) 236.949,54.912 236.949,54.428 v1(236.939,54.419) 236.939,54.379 236.782,54.222 C659.1@236.782,53.356
  Top Layer 1 _Signal w0.381: U49.9@234.691,56.455 235.758,56.455 236.381,57.077 236.576,57.077 v1(236.58,57.081)
  Top Layer 1 _Signal w0.508: v1(237.082,98.344) 236.958,98.468 R254.2@236.958,99.717 236.958,100.657 ; v1(237.301,97.188) 236.675,97.188 v1(236.644,97.219) 236.644,100.342 236.958,100.657 ; C670.1@237.387,101.086 236.958,100.657 ; U47.3@239.088,34.335 240.244,34.335 v1(240.455,34.124) 240.483,34.096 v1@240.552,34.096 ; U47.9@239.088,37.335 240.363,37.335 240.66,37.632 v1(240.66,37.806) v1@240.666,37.812
  Top Layer 1 _Signal w1.016: v1(241.464,29.235) 242.072,29.842 C25.1@242.072,33.275
  L5_POWER w1.016: v1(236.566,98.43) 236.566,97.586 236.834,97.318 236.252,96.736 236.252,64.414 236.58,64.086 v1(236.58,57.081)
  L6_Signals w0.508: v1(240.455,34.124) 240.257,34.124 239.873,34.509 239.873,37.293 240.386,37.806 v1(240.66,37.806)
  Bottom Layer_Signals w0.508: v1(237.301,97.188) 236.675,97.188 v1(236.644,97.219) 236.607,97.255 v1(236.607,97.788) 236.607,98.389 v1(236.566,98.43) 236.995,98.43 v1(237.082,98.344) 237.558,97.867 244.25,97.867 246.12,99.737 v1(246.12,103.924)
  Bottom Layer_Signals w1.016: v1(236.58,57.081) 236.58,57.072 236.646,57.005 236.646,48.274 238,46.92 239.045,46.92 241.817,44.148 241.817,35.412 241.952,35.277 241.952,29.723 v1(241.464,29.235)
2V5_VSC: C627.2 C628.1 C629.1 C678.1 C679.1 C680.1 C681.1 C682.1 L28.2 R252.2 R257.2 R259.2 R261.2 R262.2 R268.2 R277.1 U50.C2 U50.C4 U50.C6 U50.C11 U50.C14 U50.E4 U50.E13 U50.H13 U50.M4 U50.M13 U50.P3 U50.P5 U50.P12 U50.P13 U59.6 U60.6 U61.6 | length 340.9
  Top Layer 1 _Signal w0.381: v1(254.078,60.006) 254.078,60 254.411,59.667 254.411,58.191 254.715,57.887 255.396,57.887 255.904,57.379 U50.P3@255.919,57.379 255.934,57.379 256.442,56.872 256.715,56.872 ; U50.P12@255.919,48.379 U50.P13@255.919,47.379 255.934,47.379 256.426,46.887 257.123,46.887 ; U50.P5@255.919,55.379 255.934,55.379 256.348,55.793 v1(256.382,55.793) 256.386,55.797 256.386,56.15 256.427,56.191 256.427,56.583 256.715,56.872 ; U50.M13@257.919,47.379 257.919,47.364 v1(257.412,47.872) 257.411,47.175 257.123,46.887 ; U50.M4@257.919,56.379 257.904,56.379 257.412,56.872 256.715,56.872 ; U50.H13@261.919,47.379 261.427,46.887 257.123,46.887 ; U50.E13@264.919,47.379 265.409,46.889 v1(265.426,46.889) 265.428,46.887 266.396,46.887 266.904,46.379 U50.C14@266.919,46.379 ; U50.E4@264.919,56.379 264.934,56.379 265.426,55.887 266.445,55.887 266.472,55.914 v1(266.477,55.914) ; v1(266.399,53.931) 266.456,53.931 U50.C6@266.904,54.379 ; v1(266.445,48.971) 266.449,48.974 266.499,48.974 266.904,49.379 U50.C11@266.919,49.379 ; v1(266.453,57.913) U50.C2@266.919,58.379 ; U50.C6@266.919,54.379 U50.C6@266.904,54.379 ; U50.C4@266.919,56.379 266.919,56.364 266.477,55.922 v1(266.477,55.914) ; v1(266.477,55.914) 266.477,55.909 266.427,55.858 266.427,54.886 266.909,54.405 266.909,54.384 U50.C6@266.904,54.379
  Top Layer 1 _Signal w0.508: R277.1@59.768,122.854 62.931,126.017 83.047,126.017 86.313,122.75 v1(86.313,121.299) 86.313,120.499 84.835,119.021 U59.6@84.835,118.879 ; U60.6@80.473,113.566 81.371,113.566 v1(81.416,113.521) ; U61.6@89.264,118.849 89.264,118.707 89.318,118.653 89.46,118.653 89.619,118.494 90.192,118.494 v1(90.209,118.477) ; 220.659,102.622 220.956,102.324 221.293,102.324 ; R268.2@222.566,102.324 221.293,102.324 ; v1(254.078,60.006) 247.624,60.006 239.659,67.97 231.668,67.97 221.544,78.094 221.544,86.014 221.565,86.035 221.565,88.2 221.532,88.233 221.532,98.093 C678.1@222.652,99.213 221.523,99.213 220.92,99.816 220.92,101.951 221.293,102.324
  Top Layer 1 _Signal w0.635: 220.659,102.622 220.543,102.738 220.543,111.326 223.178,113.961 C682.1@227.218,113.961
  Top Layer 1 _Signal w0.762: R261.2@254.632,36.714 258.638,36.714 v1(258.665,36.688) v1(259.704,36.688)
  L3_Signals w0.381: v1(256.382,55.793) 258.244,53.931 v1(266.399,53.931) 266.399,53.926 266.445,53.88 v1(266.445,48.971)
  L5_POWER w0.762: v1(90.209,118.477) 90.437,118.477 90.584,118.329 91.135,118.329 91.248,118.442 220.997,118.442 225.332,114.108 v1(225.404,114.108)
  Bottom Layer_Signals w0.381: v1(261.473,46.933) 265.377,46.933 265.421,46.889 v1(265.426,46.889) 265.426,47.95 v1@266.445,48.97 ; R252.2@266.163,58.554 266.305,58.411 266.305,58.065 266.453,57.918 v1(266.453,57.913) 266.453,55.943 266.477,55.919 v1(266.477,55.914)
  Bottom Layer_Signals w0.508: v1(81.416,113.521) 81.416,118.528 84.187,121.299 v1(86.313,121.299) 87.703,119.909 87.703,119.897 88.018,119.582 88.03,119.582 89.135,118.477 v1(90.209,118.477)
  Bottom Layer_Signals w0.762: v1(259.704,36.688) 259.704,45.164 v1(261.473,46.933)
3V3: C6.2 C7.2 C8.2 C9.2 C19.1 C343.2 C352.2 C437.2 C453.2 C488.2 C489.1 C567.1 C568.2 C569.2 C570.2 C571.2 C572.2 C573.2 C574.2 C590.2 C592.2 C641.1 C642.1 C645.1 C646.1 C684.1 C686.1 FB25.1 IC1.11 IC2.11 IC.11 L14.2 P2.4 R21.1 R22.1 R145.2 R188.2 R194.2 R195.2 R196.2 R203.2 R214.2 R272.2 R276.2 R278.2 R279.2 R280.2 R281.2 R282.2 R284.2 R398.2 R401.2 TP9.1 U4.F2 U4.F3 U4.F4 U4.F5 U4.F6 U4.F7 U4.F8 U4.F9 U35.1 U35.11 U35.20 U35.30 U35.38 U35.44 U35.45 U35.49 U35.53 U35.54 U41.8 U43.9 U44.1 U44.2 U44.8 U44.9 U44.47 U54.1 U55.1 U56.1 U57.1 U58.1 U59.1 U60.1 U61.1 U63.8 Y3.1 Y3.6 | length 627.9
  Top Layer 1 _Signal w0.254: v1(17.747,117.327) U35.49@18.994,117.327 19.666,117.327 19.726,117.388 ; C573.2@22.547,120.416 22.551,120.412 22.551,119.321 22.596,119.276 22.596,118.783 23.515,117.864 25.045,117.864 25.682,118.501 26.117,118.501 U35.30@26.144,118.528 ; U35.11@23.769,111.973 U35.11@23.769,112.153
  Top Layer 1 _Signal w0.305: 19.726,117.388 20.169,117.831 U35.44@20.169,119.303
  Top Layer 1 _Signal w0.381: U35.11@23.795,111.906 23.795,110.99 24.142,110.643 24.145,110.643 24.305,110.482 24.305,110.479 24.827,109.957 24.974,109.957 R196.2@25.059,109.873 ; U35.20@26.144,114.528 27.271,114.528 27.307,114.492 v1(27.313,114.492) 27.309,114.488 27.309,114.254 27.173,114.118 C570.2@27.173,113.931 ; TP9.1@27.093,120.813 27.135,120.771 27.135,119.949 27.173,119.911 C574.2@27.173,119.646 ; R278.2@73.957,117.818 74.308,117.468 74.308,117.43 74.469,117.269 74.956,117.269 74.967,117.259 75,117.259 75.278,116.981 75.278,116.906 75.648,116.535 ; U57.1@75.658,115.799 75.648,115.809 75.648,116.535 ; R280.2@78.376,117.636 R280.2@78.355,117.657 78.311,117.613 75.871,117.613 75.648,117.39 75.648,116.535 ; U61.1@89.264,121.049 90.567,121.049 ; v1(273.681,30.132) 273.687,30.132 273.793,30.238 274.413,30.238 FB25.1@274.616,30.442 ; v1(280.168,97.177) 280.168,97.173 U4.F7@280.672,96.669 ; v1(280.222,101.219) U4.F2@280.672,101.669 ; v1(280.34,103.604) 280.34,103.599 280.672,103.268 U4.F2@280.672,101.669 ; v1(290.801,90.49) 283.929,90.49 280.672,93.747 U4.F9@280.672,94.669 U4.F8@280.672,95.669 U4.F7@280.672,96.669 ; U4.F7@280.672,96.669 U4.F6@280.672,97.669 U4.F5@280.672,98.669 U4.F4@280.672,99.669 U4.F3@280.672,100.669 U4.F2@280.672,101.669
  Top Layer 1 _Signal w0.4: U44.47@58.789,111.859 60.985,111.859 61.513,112.388 61.513,115.745 60.456,116.802
  Top Layer 1 _Signal w0.457: v1(17.913,108.905) 17.942,108.905 18.21,109.173 18.21,109.872 R203.2@18.257,109.918 ; 19.348,110.946 19.293,110.891 19.273,110.891 18.931,110.549 18.931,110.501 18.395,109.965 18.303,109.965 18.296,109.958 18.296,109.872 18.303,109.872 18.303,109.413 18.571,109.145 R195.2@22.373,109.145 22.373,109.138 24.808,106.703 U63.8@24.808,103.865 ; R195.2@22.374,109.146 R194.2@23.745,109.147 ; R194.2@23.745,109.147 23.778,109.18 24.366,109.18 R196.2@25.059,109.873
  Top Layer 1 _Signal w0.508: U41.8@10.984,109.266 10.984,108.966 11.979,107.971 16.179,107.971 v1(16.398,108.19) ; R188.2@16.565,120.431 16.64,120.506 16.64,121.121 v1(17.003,121.484) ; v1(17.978,115.46) 18.977,115.46 ; v1(19.234,119.815) 19.287,119.815 19.769,119.332 U35.45@19.769,119.303 ; C489.1@22.271,86.979 22.297,87.005 26.503,87.005 C343.2@26.529,87.031 ; P2.4@40.67,128.751 40.67,121.582 43.869,118.383 C684.1@43.869,114.181 ; 60.456,116.802 C646.1@64.88,121.226 64.454,121.651 C642.1@62.399,121.651 ; C645.1@66.203,121.334 66.203,120.476 68.861,117.818 R278.2@73.957,117.818 73.783,117.644 73.783,116.397 73.82,116.36 73.82,113.039 73.927,112.931 73.927,112.352 R279.2@73.948,112.331 73.969,112.31 73.969,111.699 74.779,110.889 78.081,110.889 78.511,111.319 ; U56.1@75.395,121.191 75.395,121.049 78.056,118.389 78.056,117.955 R280.2@78.355,117.657 ; R280.2@78.376,117.636 78.376,117.115 78.937,116.554 80.134,116.554 80.419,116.268 80.419,115.82 U60.1@80.473,115.766 ; R282.2@78.511,112.389 78.511,111.102 78.809,110.804 82.539,110.804 83.028,111.293 83.028,112.135 83.111,112.218 83.111,112.409 R276.2@83.132,112.43 ; U58.1@79.894,120.939 79.894,121.329 80.558,121.994 82.482,121.994 82.779,121.696 82.779,118.546 82.997,118.329 82.997,118.046 R281.2@83.231,117.812 ; U60.1@80.473,115.908 82.262,117.696 82.925,117.696 83.019,117.791 83.21,117.791 R281.2@83.231,117.812 ; v1(81.442,101.577) 82.808,100.21 U43.9@82.808,97.247 ; 82.997,119.699 83.588,120.291 84.495,120.291 84.781,120.576 84.781,121.025 U59.1@84.835,121.079 ; 85.01,116.233 84.428,116.815 84.101,116.815 83.252,117.663 83.252,117.791 R281.2@83.231,117.812 ; U55.1@85.064,115.73 85.064,116.686 86.137,117.759 R284.2@87.656,117.759 87.677,117.738 87.677,116.341 C590.2@87.803,116.215 91.014,116.215 91.398,116.599 91.398,120.219 90.567,121.049
  Top Layer 1 _Signal w0.635: C19.1@18.903,92.133 18.903,92.407 19.607,93.111 R145.2@19.607,93.161 ; C686.1@43.966,112.879 43.966,110.263 44.552,109.677 46.892,109.677 47.765,108.804 47.765,107.226 47.306,106.768 R272.2@47.089,106.768 47.065,106.792 46.133,106.792 U54.1@46.015,106.909
  Top Layer 1 _Signal w0.762: R145.2@19.607,93.111 20.027,93.111 ; U63.8@24.808,103.865 23.425,103.865 22.7,103.139 22.7,95.697 20.114,93.111 20.027,93.111 ; C343.2@26.529,87.031 26.675,87.177 28.239,87.177 28.685,87.624 28.685,91.552 27.127,93.111 20.027,93.111 ; TP9.1@27.093,120.813 34.164,120.813 36.593,118.383 43.869,118.383 50.357,118.383 52.665,116.075 ; C592.2@52.665,114.803 52.665,116.075 ; 57.923,113.005 57.923,116.232 ; 60.456,116.802 58.494,116.802 57.923,116.232 ; 90.567,121.049 93.444,121.049 v1(93.46,121.033) ; Y3.6@267.859,62.079 Y3.1@267.859,63.679 270.481,63.679 v1(270.648,63.846) ; 52.665,116.075 52.665,116.838 53.711,117.884 56.866,117.884 57.923,116.826 57.923,116.232
  L3_Signals w0.762: v1(270.648,63.846) 271.365,63.129 271.365,32.448 v1(273.681,30.132)
  L5_POWER w0.762: v1(93.46,121.033) 93.582,120.911 178.053,120.911 178.965,119.999 268.767,119.999 280.34,108.425 v1(280.34,103.604) ; v1(270.648,63.846) 272.895,66.092 279.658,66.092 283.735,70.17 283.735,88.228 285.948,90.441 v1(288.75,90.441)
  Bottom Layer_Signals w0.254: v1(290.801,90.49) R21.1@292.547,90.491
  Bottom Layer_Signals w0.381: R401.2@271.96,8.448 271.96,11.076 270.476,12.561 270.476,28.116 272.491,30.132 v1(273.681,30.132) ; C7.2@280.167,98.048 280.167,99.034 C8.2@280.15,99.051 280.15,100.133 C9.2@280.236,100.219 280.222,100.234 v1(280.222,101.219) 280.222,102.365 280.286,102.429 280.286,102.577 C6.2@280.402,102.693
  Bottom Layer_Signals w0.508: v1(16.398,108.19) 17.197,108.19 v1(17.913,108.905) ; v1(17.003,121.484) 18.515,121.484 19.234,120.764 v1(19.234,119.815) ; 17.687,117.073 17.687,115.752 v1(17.978,115.46) 20.391,115.46 21.107,114.744 21.107,111.619 20.81,111.321 v1(19.609,111.321) ; v1(17.747,117.327) 19.22,118.801 22.486,118.801 25.271,116.015 25.271,115.977 26.752,114.496 27.309,114.496 v1(27.313,114.492) ; v1(78.955,110.894) 78.955,102.396 79.774,101.577 v1(81.442,101.577) 82.117,102.252 R214.2@82.117,103.123 ; R401.2@271.96,8.448 283.098,8.448 R398.2@283.301,8.245
5V: C194.2 C206.2 C330.1 C347.1 C348.1 C349.1 C351.1 C354.1 C355.2 C438.1 C447.1 C483.1 C484.1 C603.1 C604.1 C605.1 C667.1 C668.1 C669.1 C675.1 C676.1 C677.1 L6.2 R136.2 R140.2 R255.2 R269.2 R334.1 U36.1 U38.1 U39.7 U39.8 U39.12 U51.1 U52.7 U52.8 U52.12 U53.1 | length 328.4
  Top Layer 1 _Signal w0.4: U39.12@233.902,84.322 233.927,84.297 234.55,84.297 235.778,83.068 235.951,83.068 ; R255.2@236.185,105.433 236.217,105.465 v1(236.217,106.663) ; R140.2@247.035,90.062 247.055,90.082 248.128,90.082 C355.2@248.148,90.103
  Top Layer 1 _Signal w0.508: C194.2@44.492,96.079 46.206,96.079 46.427,95.858
  Top Layer 1 _Signal w0.66: R334.1@45.827,95.838 45.847,95.858 46.427,95.858 U38.1@47.218,95.858 ; U38.1@47.218,95.859 U38.1@47.395,95.859 ; R269.2@221.92,105.038 v1@221.92,107.573 ; v1@221.92,107.642 221.882,107.679 v1(221.882,108.267) v1@221.92,108.305 ; v1(225.655,102.661) 225.781,102.787 226.902,102.787 227.05,102.934 C677.1@227.05,103.059 ; v1(225.841,97.612) C675.1@226.711,98.482 ; C603.1@238.065,78.442 237.225,79.281 235.658,79.281 233.984,77.607 233.984,70.172 235.502,68.653 v1(237.478,68.653) 239.177,68.653 ; v1(238.17,95.647) 238.181,95.636 239.848,95.636 ; C604.1@238.205,74.285 238.39,74.1 v1(239.61,74.1) ; 239.876,95.608 240.087,95.608 v1(240.616,96.138) C669.1@240.616,102.377 240.535,102.458 v1(240.535,103.48) ; R140.2@247.035,90.062 247.035,90.084 R140.2@247.077,90.126
  Top Layer 1 _Signal w1.016: C483.1@40.324,95.03 C484.1@40.324,97.293 40.324,98.442 40.92,99.038 42.978,99.038 45.827,96.188 R334.1@45.827,95.838 ; U38.1@47.395,95.904 49.707,98.216 62.136,98.216 67.486,92.866 83.824,92.866 v1(83.863,92.828) ; C347.1@225.608,84.287 224.915,84.287 224.32,83.692 224.32,80.812 224.915,80.216 233.984,80.216 ; 233.984,77.607 233.984,80.216 ; v1(240.616,96.138) 240.616,95.783 243.104,93.295 243.104,90.323 245.097,88.331 C354.1@248.157,88.331 ; C348.1@248.155,86.159 239.042,86.159 235.951,83.068 233.984,81.102 233.984,80.216
  L3_Signals w0.66: v1(237.478,68.653) 239.63,70.806 239.63,74.08 v1(239.61,74.1)
  L5_POWER w1.27: v1(83.863,92.828) 104.925,113.89 218.931,113.89 221.92,110.901 v1@221.92,108.305
  Bottom Layer_Signals w0.6: v1(236.217,106.663) 238.561,106.663 240.535,104.689 v1(240.535,103.48)
  Bottom Layer_Signals w0.66: v1(221.885,107.607) 224.649,107.607 225.719,106.536 225.811,106.536 226.171,106.177 226.171,106.085 226.174,106.081 226.174,103.18 v1(225.655,102.661) ; v1(225.745,99.181) 225.745,97.708 v1(225.841,97.612) 234.131,97.612 236.106,95.636 v1@238.17,95.636
  other v1: 225.735,98.467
